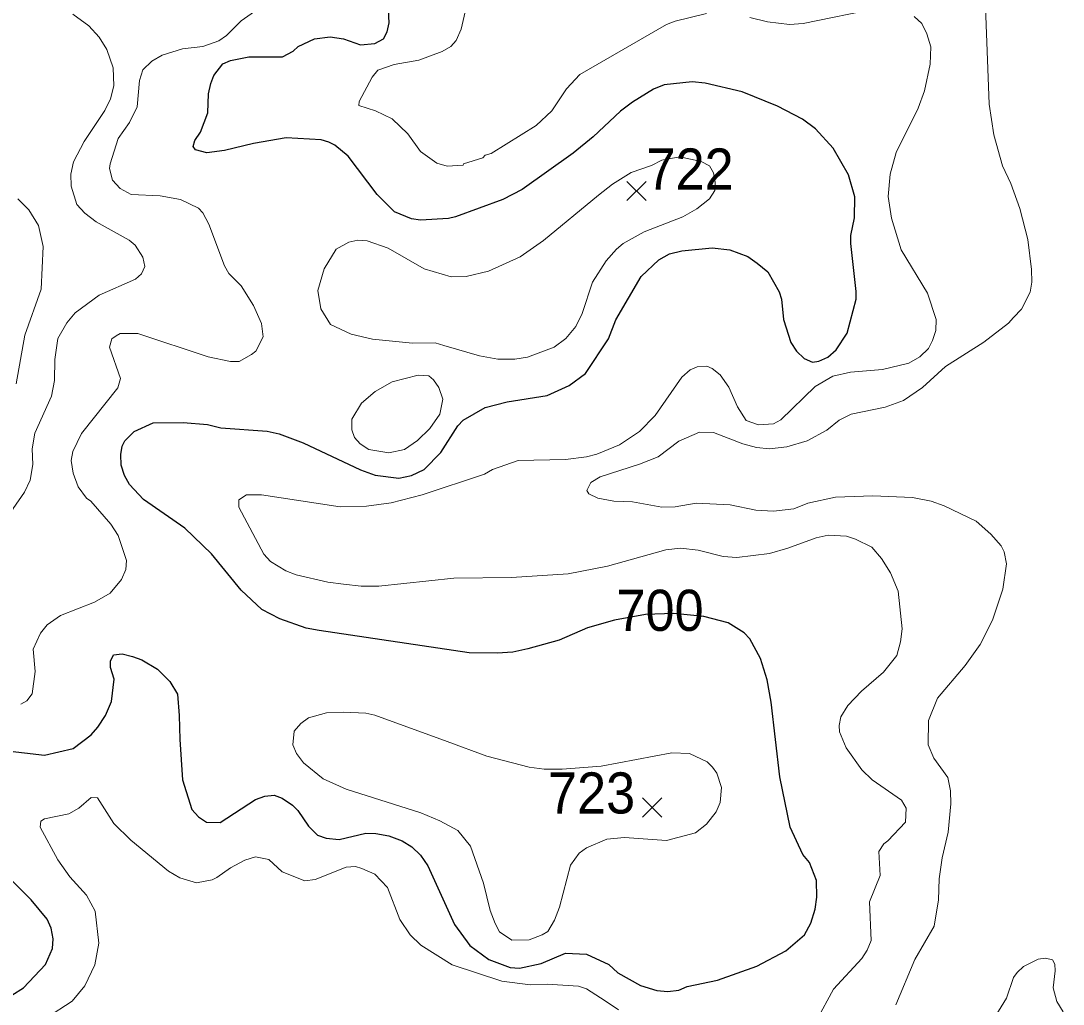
# Model space of a CAD drawing. Extents: x 294.2 to 320.3, y 7482.7 to 7510.7.
# Drawn here: x 313.131 to 315.158, y 7503.085 to 7504.998 of the extents above; entities that cross this region are included whole.
import ezdxf
from ezdxf.enums import TextEntityAlignment as Align

# ---------------------------------------------------------------- set-up
doc = ezdxf.new("R2010")
doc.units = 0
doc.header["$LTSCALE"] = 0.032
for name, color, linetype, lineweight in [('1', 7, 'Continuous', 25), ('2', 7, 'Continuous', 13), ('21', 7, 'Continuous', 25)]:
    doc.layers.add(name, color=color, linetype=linetype, lineweight=lineweight)
doc.layers.add('61', color=7, linetype='Continuous')

msp = doc.modelspace()

# ---------------------------------------------------------------- linework, layer by layer
at = {"layer": '1'}
for points in [[(314.753, 7504.6553), (314.7408, 7504.6983), (314.7108, 7504.7499), (314.6765, 7504.7881), (314.6509, 7504.8064), (314.6027, 7504.8322), (314.5339, 7504.8596), (314.4618, 7504.8768), (314.4363, 7504.879), (314.382, 7504.8731), (314.3614, 7504.865), (314.3209, 7504.8397), (314.2971, 7504.822), (314.2444, 7504.772), (314.2055, 7504.7402), (314.1063, 7504.6697), (314.0686, 7504.6504), (313.9765, 7504.617), (313.9627, 7504.6132), (313.9083, 7504.6105), (313.8911, 7504.6127), (313.8578, 7504.6266), (313.824, 7504.66), (313.7674, 7504.7347), (313.7419, 7504.7563), (313.7303, 7504.7622), (313.7153, 7504.7665), (313.6471, 7504.7703), (313.5839, 7504.7595), (313.5273, 7504.7455), (313.4929, 7504.7412), (313.4707, 7504.7471), (313.4663, 7504.7536), (313.4696, 7504.7654), (313.4807, 7504.7815), (313.4951, 7504.8192), (313.4962, 7504.8562), (313.5006, 7504.8761), (313.5062, 7504.8917), (313.5239, 7504.9143), (313.5389, 7504.9208), (313.5744, 7504.9278), (313.6399, 7504.9278), (313.6609, 7504.9386), (313.6704, 7504.9477), (313.702, 7504.9628), (313.733, 7504.9665), (313.7585, 7504.9627), (313.7918, 7504.9509), (313.8195, 7504.9536), (313.8367, 7504.9627), (313.8433, 7504.9767), (313.8472, 7504.9939), (313.8445, 7505.0456)], [(314.738, 7504.3907), (314.7552, 7504.4563), (314.7558, 7504.4714), (314.7452, 7504.5649), (314.7452, 7504.5805), (314.7524, 7504.6149), (314.753, 7504.6553)], [(314.1429, 7503.1645), (314.1906, 7503.1844), (314.2311, 7503.1828), (314.2743, 7503.1629), (314.292, 7503.1462), (314.3364, 7503.1215), (314.368, 7503.1118), (314.3891, 7503.1102), (314.4107, 7503.1129), (314.4268, 7503.1199), (314.4861, 7503.1322), (314.5621, 7503.1596), (314.6186, 7503.1892), (314.6552, 7503.2204), (314.6674, 7503.243), (314.6757, 7503.2704), (314.6791, 7503.2935), (314.6785, 7503.3258), (314.6647, 7503.3607), (314.6519, 7503.3768), (314.6269, 7503.4295), (314.6069, 7503.5273), (314.5903, 7503.6725), (314.5825, 7503.7161), (314.5697, 7503.7575), (314.5486, 7503.7957), (314.5375, 7503.8076), (314.5064, 7503.8269), (314.4593, 7503.8393), (314.4007, 7503.8453), (314.3457, 7503.8431), (314.2858, 7503.8323), (314.2331, 7503.8174), (314.1781, 7503.7936), (314.117, 7503.7764), (314.0876, 7503.7699), (314.0577, 7503.7683), (314.0027, 7503.7689), (313.7115, 7503.8119), (313.6859, 7503.8167), (313.6347, 7503.8348), (313.5997, 7503.8531), (313.5597, 7503.8908), (313.502, 7503.9612), (313.4504, 7504.0113), (313.37, 7504.0672), (313.3428, 7504.0963), (313.3328, 7504.1135), (313.3262, 7504.1339), (313.3256, 7504.1543), (313.3279, 7504.1705), (313.3334, 7504.1812), (313.3517, 7504.1995), (313.3883, 7504.2162), (313.4471, 7504.2167), (313.4943, 7504.2129), (313.5203, 7504.206), (313.6102, 7504.2), (313.6335, 7504.1947), (313.68, 7504.177), (313.7915, 7504.1248), (313.8204, 7504.1145), (313.8664, 7504.1086), (313.8908, 7504.1135), (313.9152, 7504.1253), (313.9479, 7504.1586), (313.9812, 7504.2102), (313.9912, 7504.221), (314.0339, 7504.2457), (314.0771, 7504.257), (314.1548, 7504.2693), (314.1975, 7504.2887), (314.2291, 7504.3118), (314.274, 7504.3796), (314.2884, 7504.4161), (314.3377, 7504.5005), (314.3721, 7504.5328), (314.3926, 7504.5446), (314.4164, 7504.5505), (314.4752, 7504.5564), (314.5096, 7504.5526), (314.5451, 7504.5397), (314.5628, 7504.5268), (314.5839, 7504.5096), (314.6061, 7504.4709), (314.6105, 7504.4564), (314.6144, 7504.4171), (314.6282, 7504.3724), (314.6393, 7504.3552), (314.6543, 7504.3412), (314.6704, 7504.3342), (314.6826, 7504.3358), (314.7003, 7504.3439), (314.7169, 7504.3579), (314.738, 7504.3907)], [(313.0996, 7503.5788), (313.1775, 7503.5699), (313.233, 7503.5826), (313.2682, 7503.6094), (313.2809, 7503.6241), (313.2956, 7503.6471), (313.3077, 7503.6739), (313.3129, 7503.7174), (313.3058, 7503.7403), (313.3058, 7503.7525), (313.3113, 7503.7651), (313.3282, 7503.7665), (313.348, 7503.7614), (313.3665, 7503.755), (313.3971, 7503.7372), (313.4207, 7503.7129), (313.436, 7503.6886), (313.4393, 7503.6471), (313.4401, 7503.6001), (313.4453, 7503.5217), (313.4636, 7503.4641), (313.4764, 7503.4496), (313.4919, 7503.4394), (313.5191, 7503.4388), (313.5878, 7503.4835), (313.6056, 7503.4899), (313.6239, 7503.4916), (313.6394, 7503.4862), (313.6594, 7503.4722), (313.6699, 7503.462), (313.6904, 7503.4319), (313.7082, 7503.4141), (313.7248, 7503.4082), (313.7503, 7503.406), (313.8019, 7503.4179), (313.8213, 7503.4173), (313.8468, 7503.4125), (313.8729, 7503.4033), (313.8912, 7503.3915), (313.9084, 7503.3754), (313.9223, 7503.3544)], [(313.0906, 7503.0886), (313.1361, 7503.1171), (313.1794, 7503.1628), (313.1927, 7503.194), (313.1943, 7503.2128), (313.1904, 7503.2332), (313.1827, 7503.251), (313.151, 7503.2881), (313.1005, 7503.3386)], [(313.9223, 7503.3544), (313.9744, 7503.2404), (314.0043, 7503.1995), (314.0409, 7503.1721), (314.0825, 7503.1565), (314.1008, 7503.1554), (314.1429, 7503.1645)]]:
    msp.add_lwpolyline(points, dxfattribs=at)
at = {"layer": '2'}
for points in [[(313.7918, 7505.2043), (313.747, 7505.161), (313.7042, 7505.1041), (313.6678, 7505.0741), (313.5599, 7504.9981), (313.5312, 7504.9694), (313.5159, 7504.9592)], [(314.8324, 7503.084), (314.8694, 7503.1721), (314.9071, 7503.2372), (314.9154, 7503.2883), (314.9167, 7503.3292), (314.9225, 7503.3701), (314.9346, 7503.4199), (314.9397, 7503.4748), (314.9391, 7503.5003), (314.934, 7503.5264), (314.9065, 7503.5641), (314.8956, 7503.5897), (314.8963, 7503.6369), (314.9135, 7503.6803), (314.9672, 7503.7442), (314.9965, 7503.7851), (315.0208, 7503.8323), (315.0405, 7503.8923), (315.0476, 7503.9421), (315.0431, 7503.9651), (315.0374, 7503.9766), (315.0176, 7503.9996), (314.9889, 7504.0245), (314.9269, 7504.0545), (314.9014, 7504.0634), (314.865, 7504.0705), (314.7877, 7504.0743), (314.715, 7504.0717), (314.6613, 7504.0596), (314.6345, 7504.0487), (314.5949, 7504.0442), (314.5605, 7504.0462), (314.5107, 7504.0564), (314.4442, 7504.0596), (314.4034, 7504.0526), (314.3778, 7504.0519), (314.3204, 7504.0621), (314.2846, 7504.0634), (314.2533, 7504.0698), (314.2355, 7504.0781), (314.2316, 7504.0845), (314.2393, 7504.0998), (314.2578, 7504.1113), (314.3344, 7504.1356), (314.3702, 7504.1496), (314.411, 7504.1803), (314.4506, 7504.1981), (314.4781, 7504.1975), (314.5349, 7504.1752), (314.5617, 7504.1681), (314.5873, 7504.1655), (314.6205, 7504.1694), (314.66, 7504.1809), (314.6984, 7504.202), (314.7226, 7504.2211), (314.7456, 7504.2326), (314.8117, 7504.2467), (314.8473, 7504.2595), (314.8847, 7504.2845), (314.9295, 7504.3258), (315.0035, 7504.3731), (315.052, 7504.4101), (315.0616, 7504.421), (315.077, 7504.4369), (315.0936, 7504.4701), (315.0974, 7504.4899), (315.0967, 7504.5142), (315.0891, 7504.5729), (315.0738, 7504.633), (315.0565, 7504.6815), (315.0399, 7504.716), (315.0233, 7504.776), (315.0144, 7504.836), (315.0042, 7505.0939)], [(314.4647, 7505.0122), (314.4034, 7504.9975), (314.3868, 7504.9905), (314.2182, 7504.8934), (314.192, 7504.8653), (314.164, 7504.8226), (314.1333, 7504.7945), (314.0458, 7504.7397), (314.0343, 7504.7363), (314.0297, 7504.7313), (313.9918, 7504.7196), (313.9915, 7504.7172), (313.9603, 7504.7153), (313.9399, 7504.721), (313.9086, 7504.744), (313.8836, 7504.7779), (313.853, 7504.8073), (313.8211, 7504.8226), (313.7885, 7504.8334), (313.7891, 7504.8411), (313.8141, 7504.8883), (313.8256, 7504.9017), (313.8569, 7504.9132), (313.9054, 7504.9215), (313.9507, 7504.9381), (313.9673, 7504.9477), (313.9775, 7504.9598), (313.9871, 7504.9816), (314.0005, 7505.039)], [(314.798, 7505.0224), (314.6524, 7504.9924), (314.6256, 7504.9905), (314.5834, 7504.9956), (314.549, 7505.0045)], [(313.2324, 7505.0109), (313.2637, 7504.9879), (313.2835, 7504.9662), (313.2982, 7504.942), (313.3109, 7504.9062), (313.3122, 7504.8717), (313.3058, 7504.8462), (313.2943, 7504.8232), (313.2541, 7504.7632), (313.2337, 7504.7236), (313.2285, 7504.6994), (313.2292, 7504.6764), (313.2401, 7504.6406), (313.2554, 7504.624), (313.2777, 7504.6068), (313.3416, 7504.5716), (313.3537, 7504.5614), (313.3684, 7504.5385), (313.3722, 7504.5199), (313.3658, 7504.5059), (313.3544, 7504.4957), (313.2835, 7504.4644), (313.2369, 7504.4299), (313.2203, 7504.4108), (313.203, 7504.3801), (313.1973, 7504.3393), (313.1966, 7504.2984), (313.1909, 7504.2677), (313.1583, 7504.1962), (313.1532, 7504.1656), (313.1545, 7504.1349), (313.1494, 7504.1043)], [(314.7099, 7504.3067), (314.7443, 7504.3144), (314.8069, 7504.3195), (314.858, 7504.3322), (314.879, 7504.3443), (314.8962, 7504.3609), (314.9039, 7504.3763), (314.9103, 7504.3954), (314.911, 7504.4172), (314.8944, 7504.4682), (314.8433, 7504.5525), (314.8241, 7504.6138), (314.8178, 7504.6559), (314.8216, 7504.6994), (314.8331, 7504.7415), (314.8758, 7504.8283), (314.8886, 7504.8615), (314.8995, 7504.9139), (314.9008, 7504.9471), (314.8931, 7504.9726), (314.8835, 7504.9924), (314.8682, 7505.0064)], [(313.5159, 7504.9592), (313.4853, 7504.9477), (313.4457, 7504.9432), (313.4061, 7504.9311), (313.3857, 7504.9196), (313.3684, 7504.9024), (313.362, 7504.882), (313.3575, 7504.8309), (313.3422, 7504.8002), (313.3205, 7504.7689), (313.3046, 7504.7198), (313.3039, 7504.7109), (313.3097, 7504.6879), (313.3243, 7504.6719), (313.346, 7504.6604), (313.4023, 7504.6572), (313.4418, 7504.6502), (313.4769, 7504.6336), (313.4852, 7504.6246), (313.4967, 7504.6023), (313.5274, 7504.5212), (313.5357, 7504.5065), (313.5593, 7504.4822), (313.5835, 7504.444), (313.5989, 7504.4095), (313.6021, 7504.3833), (313.588, 7504.3552), (313.5797, 7504.3488), (313.5555, 7504.3354), (313.5389, 7504.3354), (313.4955, 7504.3443), (313.3588, 7504.3897), (313.3244, 7504.3897), (313.3167, 7504.3852), (313.3084, 7504.3794), (313.3033, 7504.3635), (313.325, 7504.3022), (313.3199, 7504.2843), (313.249, 7504.1956), (313.2324, 7504.1605), (313.2292, 7504.1426), (313.2331, 7504.1183), (313.2428, 7504.0914), (313.2586, 7504.0698), (313.2675, 7504.0634), (313.3064, 7504.0187), (313.3205, 7503.997), (313.3365, 7503.9485), (313.3352, 7503.9306), (313.3269, 7503.9115), (313.3046, 7503.8846), (313.2746, 7503.8674), (313.2082, 7503.8412), (313.1826, 7503.8233), (313.1692, 7503.8068), (313.1552, 7503.7761), (313.159, 7503.7327), (313.1532, 7503.6893), (313.143, 7503.6752), (313.1309, 7503.6689)], [(313.122, 7504.292), (313.1392, 7504.3865), (313.1705, 7504.4759), (313.1749, 7504.5589), (313.1654, 7504.5998), (313.1468, 7504.6304), (313.1251, 7504.6515)], [(314.6786, 7503.0534), (314.7117, 7503.1147), (314.7667, 7503.174), (314.7769, 7503.1906), (314.7845, 7503.2092), (314.7813, 7503.2845), (314.8024, 7503.3356), (314.7999, 7503.3821), (314.8094, 7503.3975), (314.8171, 7503.4032), (314.8517, 7503.4393), (314.8529, 7503.4666), (314.8437, 7503.4822), (314.7868, 7503.522), (314.7668, 7503.5409), (314.7363, 7503.5838), (314.7231, 7503.6153), (314.7225, 7503.6275), (314.7254, 7503.6442), (314.7392, 7503.6665), (314.7661, 7503.6943), (314.8086, 7503.7308), (314.8345, 7503.7636), (314.8419, 7503.7904), (314.8448, 7503.8151), (314.8369, 7503.8885), (314.8222, 7503.9242), (314.805, 7503.9523), (314.7858, 7503.974), (314.7545, 7503.99), (314.7367, 7503.9957), (314.7009, 7503.9977), (314.6779, 7503.9926), (314.6224, 7503.9721), (314.5873, 7503.9619), (314.5234, 7503.9542), (314.4966, 7503.9561), (314.4481, 7503.9683), (314.4136, 7503.9721), (314.3855, 7503.9689), (314.2719, 7503.9376), (314.1952, 7503.9223), (314.0854, 7503.9153), (313.9731, 7503.914), (313.8275, 7503.8987), (313.793, 7503.8981), (313.7585, 7503.9025), (313.7279, 7503.9063), (313.6666, 7503.9204), (313.6462, 7503.928), (313.6167, 7503.9466), (313.604, 7503.9606), (313.5548, 7504.0519), (313.5554, 7504.0666), (313.5701, 7504.0762), (313.5989, 7504.0762), (313.7521, 7504.0526), (313.8032, 7504.0539), (313.8514, 7504.0604), (313.9117, 7504.0759), (314.0331, 7504.1164), (314.0484, 7504.1254), (314.0982, 7504.1426), (314.1901, 7504.1445), (314.231, 7504.1502), (314.2514, 7504.1553), (314.2954, 7504.1732), (314.3344, 7504.1994), (314.3644, 7504.2301), (314.4168, 7504.3048), (314.4327, 7504.3188), (314.4461, 7504.3252), (314.4653, 7504.3264), (314.4755, 7504.322), (314.4908, 7504.3092), (314.5081, 7504.2856), (314.5247, 7504.2473)], [(314.5247, 7504.2473), (314.5413, 7504.2205), (314.5656, 7504.2122), (314.5949, 7504.2141), (314.6089, 7504.2218), (314.676, 7504.2869), (314.7099, 7504.3067)], [(313.1494, 7504.1043), (313.1386, 7504.0813), (313.1162, 7504.0494), (313.1098, 7504.029), (313.1079, 7503.9389), (313.0958, 7503.914), (313.0708, 7503.8815)], [(313.1813, 7503.0591), (313.2311, 7503.091), (313.2554, 7503.121), (313.2752, 7503.1619), (313.2829, 7503.204), (313.2758, 7503.2666), (313.2586, 7503.2973), (313.2267, 7503.333), (313.203, 7503.3662), (313.1685, 7503.4294), (313.1698, 7503.4415), (313.1775, 7503.446), (313.2248, 7503.4556), (313.2439, 7503.4665), (313.2682, 7503.4875), (313.2803, 7503.4869), (313.3122, 7503.4371), (313.3448, 7503.4045), (313.4182, 7503.3439), (313.4406, 7503.3311), (313.4725, 7503.3215), (313.5031, 7503.3273), (313.5121, 7503.3317), (313.5388, 7503.3509), (313.567, 7503.3656), (313.5874, 7503.372), (313.6136, 7503.3668), (313.6391, 7503.3426), (313.6832, 7503.3253), (313.7036, 7503.3279), (313.7636, 7503.3521), (313.7821, 7503.3534), (313.7943, 7503.3496)], [(313.7943, 7503.3496), (313.8198, 7503.3381), (313.8441, 7503.3126), (313.8683, 7503.25), (313.8881, 7503.22), (313.9092, 7503.2002), (313.9702, 7503.1617)], [(315.1389, 7503.1172), (315.1427, 7503.1504), (315.1421, 7503.1631), (315.1376, 7503.1715), (315.1236, 7503.1746), (315.1095, 7503.1728), (315.0808, 7503.1587)], [(313.9702, 7503.1617), (314.0663, 7503.1299), (314.1218, 7503.123), (314.1544, 7503.1242), (314.2157, 7503.1204), (314.231, 7503.1153), (314.2674, 7503.0916), (314.2936, 7503.0744)], [(315.0808, 7503.1587), (315.0687, 7503.1472), (315.0616, 7503.137), (315.0476, 7503.0968), (315.0188, 7503.0495)], [(315.158, 7503.0706), (315.1459, 7503.0904), (315.1389, 7503.1172)]]:
    msp.add_lwpolyline(points, dxfattribs=at)
for points in [[(314.1023, 7504.5387), (314.0407, 7504.511), (313.9973, 7504.5008), (313.9679, 7504.5001), (313.9156, 7504.5154), (313.8454, 7504.5557), (313.8045, 7504.5703), (313.7866, 7504.571), (313.7687, 7504.5672), (313.7444, 7504.5538), (313.7208, 7504.5155), (313.7087, 7504.4733), (313.7144, 7504.4375), (313.7336, 7504.4076), (313.7738, 7504.3884), (313.8147, 7504.3788), (313.8926, 7504.3711), (313.9366, 7504.3718), (313.9539, 7504.3667), (314.0229, 7504.3463), (314.0586, 7504.3399), (314.0918, 7504.3399), (314.1161, 7504.3437), (314.1684, 7504.3635), (314.1908, 7504.3801), (314.2105, 7504.4037), (314.2227, 7504.4286), (314.2425, 7504.4899), (314.2693, 7504.5314), (314.2897, 7504.5537), (314.3025, 7504.5646), (314.3434, 7504.5876), (314.4187, 7504.617), (314.4455, 7504.6323), (314.4704, 7504.6514), (314.4804, 7504.6679), (314.4812, 7504.6844), (314.478, 7504.7025), (314.4702, 7504.7159), (314.4544, 7504.7245), (314.4128, 7504.7332), (314.3774, 7504.7269), (314.3577, 7504.7167), (314.3178, 7504.7031), (314.2814, 7504.6802), (314.2546, 7504.6591), (314.1473, 7504.5704)], [(313.7936, 7504.2543), (313.7751, 7504.2231), (313.7745, 7504.2026), (313.7802, 7504.1873), (313.7911, 7504.1752), (313.8077, 7504.1643), (313.8466, 7504.1579), (313.8773, 7504.1643), (313.9028, 7504.1815), (313.9264, 7504.2052), (313.9462, 7504.2326), (313.952, 7504.262), (313.9443, 7504.285), (313.9334, 7504.2997), (313.9245, 7504.3073), (313.9041, 7504.3086), (313.853, 7504.2958), (313.8204, 7504.2767)], [(313.9603, 7503.596), (313.8198, 7503.6478), (313.8019, 7503.6516), (313.7585, 7503.6535), (313.7253, 7503.6522), (313.6908, 7503.6426), (313.6755, 7503.6312), (313.6627, 7503.6165), (313.6602, 7503.5896), (313.6672, 7503.5731), (313.6806, 7503.5545), (313.7189, 7503.5239), (313.7636, 7503.5035), (313.9092, 7503.4575), (313.9462, 7503.4422), (313.9807, 7503.423), (314.0056, 7503.393), (314.0311, 7503.3207), (314.0439, 7503.2679), (314.0535, 7503.2424), (314.0618, 7503.2264), (314.0861, 7503.2098), (314.1199, 7503.2104), (314.1448, 7503.22), (314.1557, 7503.227), (314.1691, 7503.2487), (314.1786, 7503.2743), (314.1997, 7503.356), (314.2169, 7503.3789), (314.231, 7503.3892), (314.2706, 7503.4064), (314.3051, 7503.4096), (314.3868, 7503.4039), (314.443, 7503.4185), (314.4647, 7503.4358), (314.4832, 7503.4594), (314.4909, 7503.4779), (314.4934, 7503.5067), (314.4845, 7503.5348), (314.4761, 7503.5463), (314.4659, 7503.5565), (314.4315, 7503.573), (314.397, 7503.5743), (314.2594, 7503.5484), (314.1838, 7503.5423), (314.1486, 7503.5424), (314.1199, 7503.5462), (314.0375, 7503.5679)]]:
    msp.add_lwpolyline(points, close=True, dxfattribs=at)
at = {"layer": '21'}
for p, q in [((314.3095, 7504.6857), (314.347, 7504.6482)), ((314.347, 7504.6857), (314.3095, 7504.6482)), ((314.3403, 7503.4866), (314.3778, 7503.4491)), ((314.3778, 7503.4866), (314.3403, 7503.4491))]:
    msp.add_line(p, q, dxfattribs=at)

# ---------------------------------------------------------------- texts
at = {"layer": '61', "width": 0.95}
for s, p in [('722', (314.4325, 7504.6697)), ('700', (314.3741, 7503.8114)), ('723', (314.241, 7503.4562))]:
    msp.add_text(s, height=0.08, dxfattribs=at).set_placement(p, align=Align.CENTER)

doc.saveas('drawing.dxf')
